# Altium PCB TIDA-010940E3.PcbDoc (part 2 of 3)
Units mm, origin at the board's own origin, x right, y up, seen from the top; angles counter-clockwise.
Board outline 71.12 x 63.5 mm, 2 copper layers (Top Layer, Bottom Layer), stack 1.382 mm thick; 136 components, 118 nets, 421 pads, 150 vias.
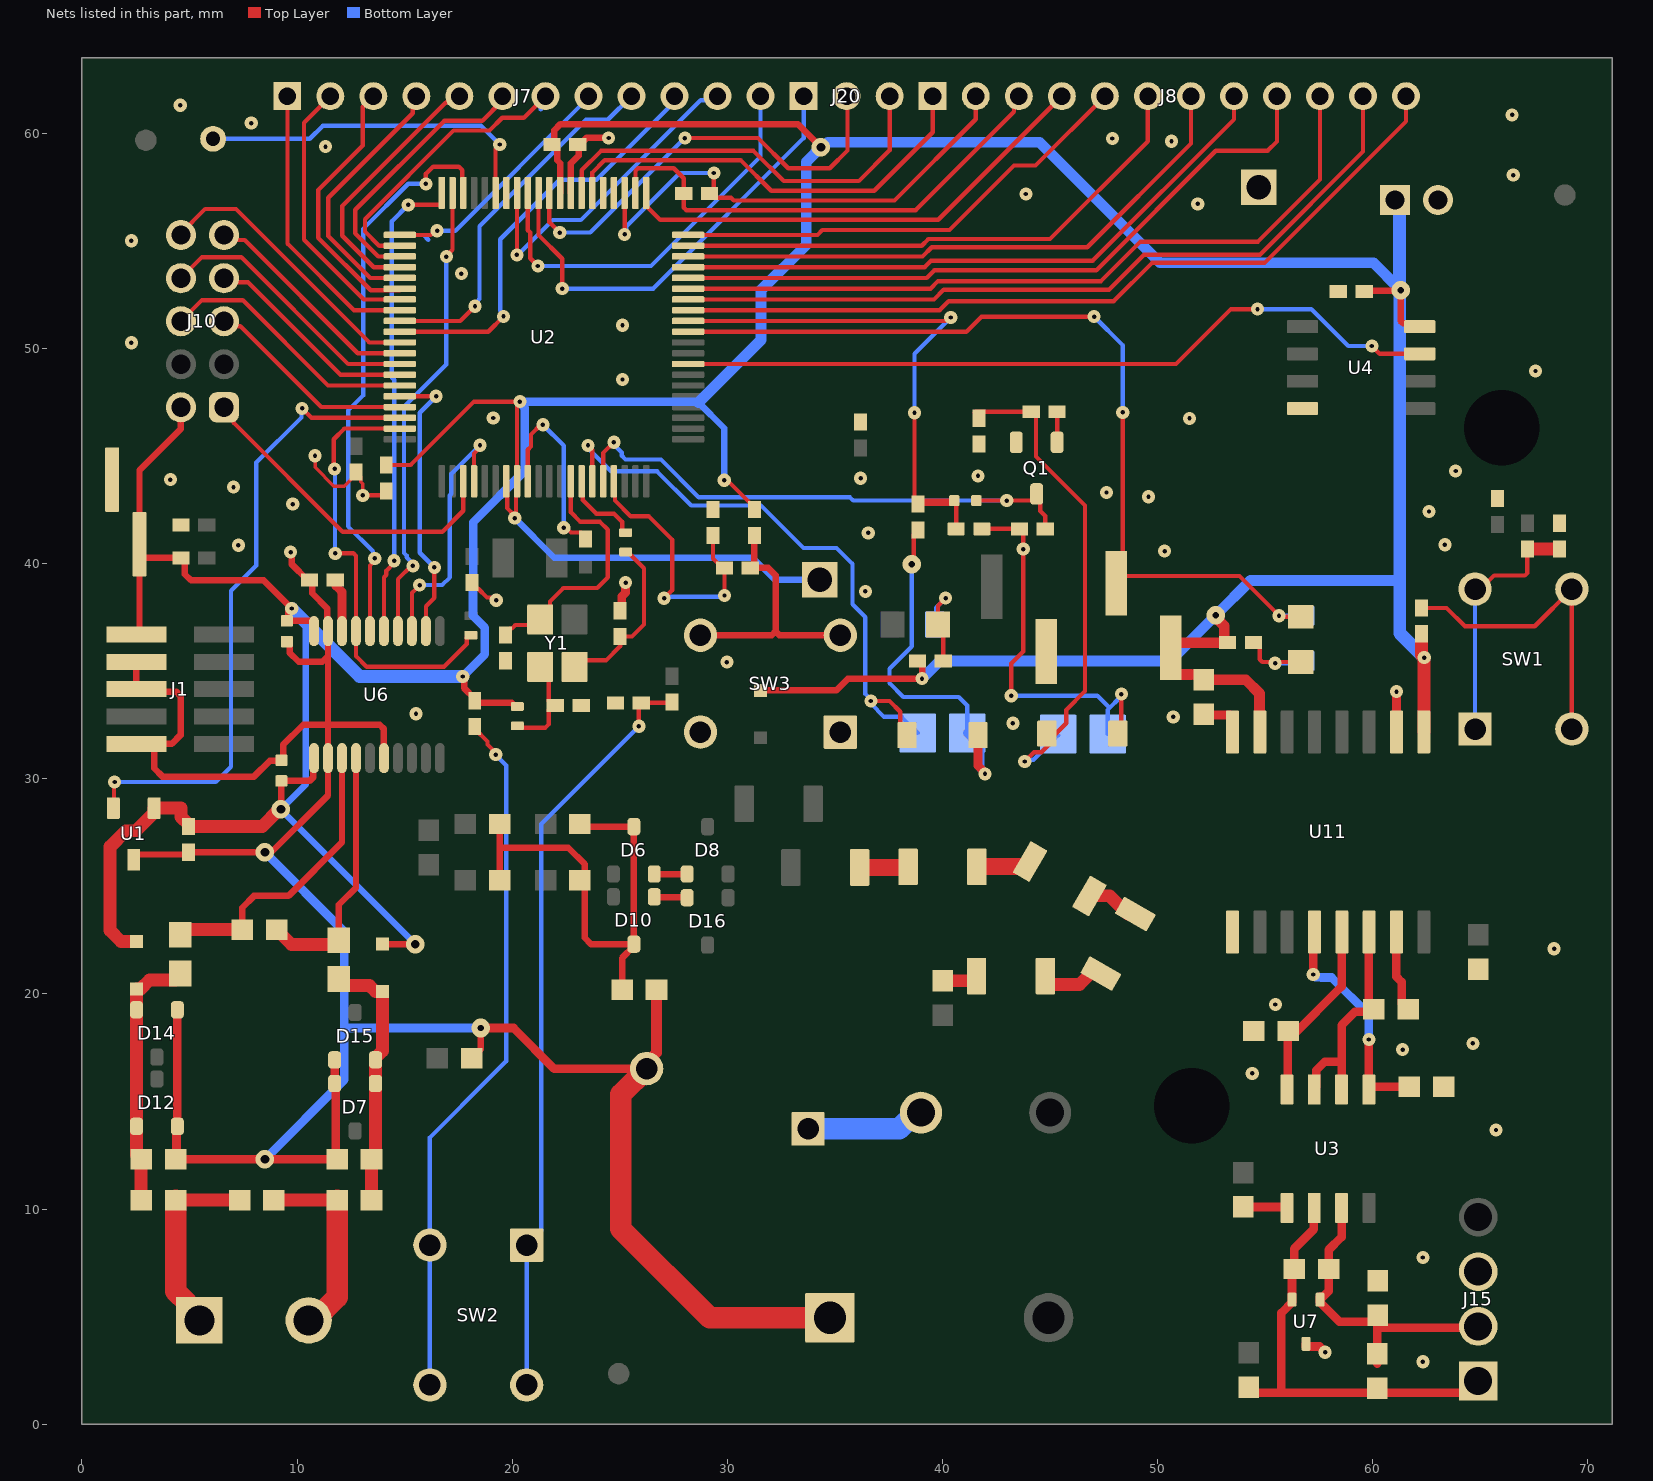
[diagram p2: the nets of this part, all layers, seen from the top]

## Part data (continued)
LBL1: library part CMP-0003625-1, "Thermal Transfer Printable Labels, 0.650\" W x 0.200\" H - 10,000 per roll", Manufacturer=Brady, Supplier Part Number 1=97C5133
Logo2: library part CMP-0074844-1
Logo3: library part CMP-0074847-1, "FCC_disclaimer"
Logo4: library part CMP-0074769-1
MP1 MP2 MP3 MP4: library part CMP-0097139-1, "Bumper Cylindrical, Flat Top 0.315\" Dia (8.00mm) Polyurethane Black", Digikey Part Number=3M156065-ND, Manufacturer=3M, Operating Temperature Range="+5°C to +52°C"
Q1: library part CMP-0000377-2, "Transistor, NPN, 30 V, 0.1 A, SOT-23", Manufacturer="ON Semiconductor", Supplier Part Number 1=BC848CLT1GOSCT-ND, Value1="0.1 A", Value2=800
R1: library part CMP-0026728-1, "RES, 220 k, 1%, 0.0625 W, 0402", Manufacturer="Yageo America", Power_W=62.5mW, Supplier Part Number 1=311-220KLRCT-ND, TempCo="100 ppm/C", Tolerance_%=1%, Value2=0.0625W, Value_Code=220k
R2: library part CMP-0026815-1, "RES, 100 k, 0.1%, 0.063 W, 0402", Manufacturer="Susumu Co Ltd", Power_W=63mW, Supplier Part Number 1=RG10P100KBCT-ND, TempCo="25 ppm/C", Tolerance_%=0.1%, Value2=0.063W, Value_Code=100k
R3: library part CMP-0049856-1, "Var MOV 460VAC/615VDC 5000A 750V Thru-Hole Radial Bulk", Clamping Voltage=1240V, Digikey Part Number=495-6498-ND, Manufacturer=TDK, Mouser Part Number=871-B72214S2461K101, Operating Temperature Range="-40°C to +105°C", ValueDisplayed=260pF, Varistor Voltage=750V, Voltage Tolerance=10%
R4 R6 R7 R74 R81: library part CMP-0025874-4, "RES, 0, 5%, 0.1 W, AEC-Q200 Grade 0, 0603", Manufacturer=Panasonic, Power_W=100mW, Supplier Part Number 1=P0.0GCT-ND, TempCo="600 ppm/C", Tolerance_%=5%, Value2=0.1W, Value_Code=0000, ValueDisplayed=0
R5 R9: library part CMP-0026658-1, "RES, 10.0 k, 1%, 0.1 W, 0402", Manufacturer=Panasonic, Power_W=100mW, Supplier Part Number 1=P10.0KLCT-ND, TempCo="100 ppm/C", Tolerance_%=1%, Value2=0.1W, Value_Code=10k0, ValueDisplayed=10.0k
R10 R11: library part CMP-0026729-1, "RES, 2.20 k, 1%, 0.063 W, 0402", Manufacturer="Yageo America", Power_W=63mW, Supplier Part Number 1=311-2.20KLRCT-ND, TempCo="100 ppm/C", Tolerance_%=1%, Value2=0.063W, Value_Code=2k20, ValueDisplayed=2.20k
R12 R13: library part CMP-0026940-2, "RES, 4.7 M, 5%, 0.063 W, AEC-Q200 Grade 0, 0402", Manufacturer=Vishay-Dale, Power_W=63mW, Supplier Part Number 1=541-4.7MJCT-ND, TempCo="200 ppm/C", Tolerance_%=5%, Value2=0.063W, Value_Code=4M70, ValueDisplayed=4.7M
R14: library part CMP-0026852-3, "RES, 1.0 k, 5%, 0.063 W, AEC-Q200 Grade 0, 0402", Manufacturer=Vishay-Dale, Power_W=63mW, Supplier Part Number 1=541-1.0KJCT-ND, TempCo="200 ppm/C", Tolerance_%=5%, Value2=0.063W, Value_Code=1k00, ValueDisplayed=1.0k
R15: library part CMP-0094948-1, "0 Ohms Jumper 0.1W, 1/10W Chip Resistor 0402 (1005 Metric) - Thick Film", Digikey Part Number=2679-CR0402-10W-000TTR-ND, Manufacturer=Venkel, Operating Temperature Range="-55°C to +155°C", Power_W=100mW
R16: library part CMP-0121809-1, "8.06 kOhms ±0.1% 0.063W, 1/16W Chip Resistor 0402 (1005 Metric) Automotive AEC-Q200 Thin Film", Digikey Part Number=P18117CT-ND, Manufacturer=Panasonic, Mouser Part Number=667-ERA-2ARB8061X, Operating Temperature Range="-55°C to +155°C", Power_W=63mW, TempCo=10ppm/°C, Tolerance_%=0.1%
R17: library part CMP-0026743-1, "RES, 820, 1%, 0.063 W, 0402", Manufacturer="Yageo America", Power_W=63mW, Supplier Part Number 1=311-820LRCT-ND, TempCo="100 ppm/C", Tolerance_%=1%, Value2=0.063W, Value_Code=820R, ValueDisplayed=820
R18 R86 R87: library part CMP-0026725-1, "RES, 1.00 k, 1%, 0.0625 W, 0402", Manufacturer="Yageo America", Power_W=62.5mW, Supplier Part Number 1=311-1.00KLRCT-ND, TempCo="100 ppm/C", Tolerance_%=1%, Value2=0.0625W, Value_Code=1k00, ValueDisplayed=1.00k
R19: library part CMP-0026680-1, "RES, 220, 1%, 0.1 W, AEC-Q200 Grade 0, 0402", Manufacturer=Panasonic, Power_W=100mW, Supplier Part Number 1=P220LCT-ND, TempCo="100 ppm/C", Tolerance_%=1%, Value2=0.1W, Value_Code=220R, ValueDisplayed=220
R20: library part CMP-0026979-3, "RES, 820, 5%, 0.063 W, AEC-Q200 Grade 0, 0402", Manufacturer=Vishay-Dale, Power_W=63mW, Supplier Part Number 1=541-820JCT-ND, TempCo="200 ppm/C", Tolerance_%=5%, Value2=0.063W, Value_Code=820R, ValueDisplayed=820
R21 R22 R23 R28 R29 R30: library part CMP-0018811-2, "RES, 330 k, 0.1%, 1 W, 1206", Manufacturer="Vishay Draloric", Power_W=1W, Supplier Part Number 1=541-2312-1-ND, TempCo="25 ppm/C", Tolerance_%=0.1%, Value_Code=330k
R24: library part CMP-0085526-3, "RES, 470, 5%, 5 W, AEC-Q200 Grade 0, Dia 7.5mm", Manufacturer=Vishay-Bccomponents, Power_W=5W, Tolerance_%=5%, Value_Code=470R, ValueDisplayed=470
R25 R26 R27: library part CMP-0120020-1, "0 Ohms Jumper Chip Resistor 0402 (1005 Metric) Metal Element", Digikey Part Number=36-5113-1-ND, Manufacturer="Keystone Electronics", Mouser Part Number=534-5113, Operating Temperature Range=to, Part Number=5113
R31 R36: library part CMP-0093507-1, "0 Ohms Jumper 1W Chip Resistor 1206 (3216 Metric) Automotive AEC-Q200, Current Sense Thick Film", Digikey Part Number=PMR18EZPJ000-ND, Manufacturer="Rohm Semiconductor", Max Current=38.7A, Mouser Part Number=755-PMR18EZPJ000, Operating Temperature Range="-55°C to +155°C"
R32 R33 R34 R35: library part CMP-0022895-5, "RES, 1.00 k, 1%, 0.1 W, 0603", Manufacturer=Yageo, Power_W=100mW, Supplier Part Number 1=311-1.00KHRCT-ND, TempCo="100 ppm/C", Tolerance_%=1%, Value2=0.1W, Value_Code=1k00, ValueDisplayed=1.00k
R37 R38: library part CMP-0092692-1, "RES SMD 0 OHM JUMPER 1/8W 0805", Digikey Part Number=311-0.0CRCT-ND, Manufacturer=Yageo, Mouser Part Number=603-RC0805FR-070RL, Operating Temperature Range="-55°C to +155°C", Power_W=125mW, Tolerance_%=1%
R46 R54: library part CMP-0025698-4, "RES, 100 k, 5%, 0.1 W, AEC-Q200 Grade 0, 0603", Manufacturer=Vishay-Dale, Power_W=100mW, Supplier Part Number 1=541-100KGCT-ND, TempCo="200 ppm/C", Tolerance_%=5%, Value2=0.1W, Value_Code=100k
R52 R55: library part CMP-0025817-4, "RES, 4.7 k, 5%, 0.1 W, AEC-Q200 Grade 0, 0603", Manufacturer=Vishay-Dale, Power_W=100mW, Supplier Part Number 1=541-4.7KGCT-ND, TempCo="200 ppm/C", Tolerance_%=5%, Value2=0.1W, Value_Code=4k70, ValueDisplayed=4.7k
R56: library part CMP-0024624-2, "RES, 120, 0.5%, 0.1 W, 0603", Manufacturer="Yageo America", Power_W=100mW, TempCo="50 ppm/C", Tolerance_%=0.5%, Value2=0.1W, Value_Code=120R, ValueDisplayed=120
R88: library part CMP-0026935-3, "RES, 47 k, 5%, 0.063 W, AEC-Q200 Grade 0, 0402", Manufacturer=Vishay-Dale, Power_W=63mW, Supplier Part Number 1=541-47KJCT-ND, TempCo="200 ppm/C", Tolerance_%=5%, Value2=0.063W, Value_Code=47k0, ValueDisplayed=47k
SW1 SW2 SW3: library part CMP-0008295-1, "Switch Tactile N.O. SPST Round Button PC Pins 0.05A 50VDC 2.45N Thru-Hole", Coil Resistance_ohm=100mΩ, Contact Current Rating=50mA, Digikey Part Number=EG1866-ND, Manufacturer=E-Switch, Mouser Part Number=612-TL1105D-250, Operating Force=250gf, Operating Temperature Range="-20°C to +70°C"
TP1: library part CMP-0055058-1, "PCB Pin, 0.46 Dia, Gold, TH", Manufacturer=Mill-Max, Supplier Part Number 1=ED1286-ND
U1: library part CMP-0078033-1, "Ultra-Low Power 1.65V to 5.5V Hall Effect Switch Sensor, DBZ0003A (SOT-23-3)", Alternate Manufacturer="Texas Instruments"
U2: library part CMP-0034581-1, Manufacturer="Texas Instruments", Operating Temperature Range=to
U3: library part CMP-0089978-1, "500 kbps RS-485 Transceivers With ±8-kV IEC ESD Protection", Manufacturer="Texas Instruments", Max Supply Voltage=5.5V, Min Supply Voltage=4.5V, Nominal Supply Current=275-440uA, Operating Temperature Range="-40°C to +125°C"
U4: library part CMP-0005381-2, "3V 8M-BIT SERIAL FLASH MEMORY WITH DUAL/QUAD SPI, SOIC-8", Manufacturer=Winbond
U6: library part CMP-0080543-1, "3-Channel, 24-Bit, Simultaneously-Sampling, Delta-Sigma ADC, PW0020A (TSSOP-20)", Alternate Manufacturer="Texas Instruments", Alternate PartNumber=ADS131M03IPWT
U7: library part CMP-0043100-2, "ESD Protection Array for AC Signal Data Interface, 2 Channels, -40 to +85 degC, 3-pin SC70 (DCK), Green (RoHS & no Sb/Br)", Breakdown Voltage(Min)(V)=+/-14, IO Capacitance(Typ)(pF)=15, IO Leakage Current(nA)=50, Manufacturer="Texas Instruments"
U11: library part CMP-0094636-1, Digikey Part Number=296-ISO6731DWRCT-ND, Manufacturer="Texas Instruments", Max Supply Voltage=5.5V, Min Supply Voltage=1.71V, Mouser Part Number=595-ISO6731DWR, Operating Temperature Range="-40°C to +125°C"
Y1: library part CMP-0085525-1, "Crystal, 16.384 MHz, 50 ppm, 10 pF, SMD", Frequency Stability="30 ppm", Frequency Tolerance="50 ppm", Frequency_Fixed=16.384MHz, Load Capacitance="10 pF", Manufacturer=Epson
Y2: library part CMP-0004693-2, "Crystal, 32.768 KHz, 12.5 pF, SMD", Frequency_Fixed=32.768kHz, Manufacturer=Epson
ZZ1: library part CMP-0003616-3
ZZ2: library part CMP-0077236-1
ZZ3: library part CMP-0077237-1
ZZ4: library part CMP-0077238-1

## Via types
v1: diameter 0.61, hole 0.203, Top Layer to Bottom Layer, tented both sides, 113 vias
v2: diameter 0.61, hole 0.203, Top Layer to Bottom Layer, 22 vias
v3: diameter 0.864, hole 0.406, Top Layer to Bottom Layer, 8 vias
v4: diameter 0.864, hole 0.3, Top Layer to Bottom Layer, tented both sides, 4 vias
v5: diameter 0.864, hole 0.406, Top Layer to Bottom Layer, tented both sides, 3 vias

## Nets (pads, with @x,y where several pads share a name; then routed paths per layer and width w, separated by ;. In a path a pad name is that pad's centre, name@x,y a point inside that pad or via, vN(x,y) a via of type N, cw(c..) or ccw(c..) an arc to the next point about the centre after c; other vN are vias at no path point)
485_D: R52.1 U3.4 U11.13 | length 8.3
  Top Layer w0.4: U3.4@56.007,15.552 56.04,15.585 56.04,18.242 R52.1@56.072,18.275 ; R52.1@56.276,18.072 58.547,20.343 U11.13@58.547,22.708
485_R: C85.2 U3.1 U11.12 | length 10.7
  Top Layer w0.4: v1(57.232,20.899) 57.232,22.663 U11.12@57.277,22.708 ; v1(59.817,17.882) U3.1@59.817,15.552 59.917,15.652 59.917,15.685 C85.2@61.7,15.685
  Bottom Layer w0.4: v1(57.232,20.899) 57.187,20.854 57.322,20.765 57.603,20.765 57.605,20.764 58.078,20.764 59.817,19.025 v1(59.817,17.882)
485_RE_DE: R55.1 U3.2 U3.3 U11.14 | length 10.5
  Top Layer w0.4: U3.3@57.277,15.552 57.377,15.652 57.377,16.458 57.758,16.839 58.447,16.839 ; U3.2@58.547,15.552 58.552,15.557 58.552,17.876 58.558,17.882 58.558,18.55 59.172,19.164 59.923,19.164 R55.1@60.038,19.279 59.817,19.5 U11.14@59.817,22.708
ACT: D1.1 J3.1 R38.1 U2.31 | length 42.4
  Top Layer w0.203: U2.31@28.178,50.774 41.113,50.774 41.813,51.475 v2(47.05,51.475) ; J3.1@48.066,39.092 48.066,39.226 J3.1@48.26,39.419 ; v2@48.371,47.147 48.371,39.53 J3.1@48.26,39.419 ; v1(55.641,37.575) 55.641,37.584 53.806,39.419 J3.1@48.26,39.419 ; v1@55.7,37.525 D1.1@56.65,37.525
  Bottom Layer w0.203: v2(47.05,51.475) 48.371,50.154 v2@48.371,47.147 ; v1(55.641,37.575) R38.1@56.7,37.575
  other v2: 48.375,47.025
ADC_DIN: U2.58 U6.16 | length 26.8
  Top Layer w0.203: U6.16@13.391,36.859 13.391,39.911 13.611,40.131 v1(13.611,40.241) ; v1(15.991,57.647) 15.991,58.113 16.327,58.449 17.517,58.449 17.687,58.279 17.687,57.265 U2.58@17.728,57.224
  Bottom Layer w0.203: v1(13.611,40.241) 13.533,40.319 13.533,40.567 12.375,41.725 12.375,47.113 13.071,47.809 13.071,55.546 15.172,57.647 v1(15.991,57.647)
ADC_DOUT: U2.60 U6.15 | length 22.5
  Top Layer w0.203: U6.15@14.041,36.859 14.041,39.368 14.155,39.482 14.155,39.665 14.511,40.021 v1(14.511,40.131) ; v1(15.172,56.673) 16.68,56.673 16.728,56.721 U2.60@16.728,57.224
  Bottom Layer w0.203: v1(14.511,40.131) 14.511,48.545 14.4,48.656 14.4,55.901 v1(15.172,56.673)
ADC_SPI0_CS1: U2.76 U6.12 | length 13.4
  Top Layer w0.2: U2.76@14.778,47.774 v1(16.468,47.774) ; U6.12@15.991,36.859 15.991,38.013 16.383,38.405 v1(16.383,39.825)
  Bottom Layer w0.2: v1(16.383,39.825) 15.705,40.503 15.705,47.012 v1(16.468,47.774)
ADC_SPI0_SCLK: U2.59 U6.14 | length 21.8
  Top Layer w0.2: U6.14@14.691,36.859 14.691,39.276 15.307,39.892 v1(15.385,39.892) ; v1(16.94,54.264) 16.94,54.298 17.228,54.586 U2.59@17.228,57.224
  Bottom Layer w0.2: v1(15.385,39.892) 15.385,40.002 15.096,40.292 15.096,40.373 14.975,40.494 14.975,47.288 16.94,49.253 v1(16.94,54.264)
BSL_Invoke: TP1.1 U2.55 | length 16.3
  Top Layer w0.2: U2.55@19.228,57.224 19.228,59.284 19.419,59.475 v2(19.424,59.475)
  Bottom Layer w0.2: TP1.1@6.1,59.74 10.593,59.74 11.203,60.35 18.549,60.35 v2(19.424,59.475)
CAP: C57.2 U6.18 | length 2.5
  Top Layer w0.4: C57.2@11.776,39.243 11.811,39.208 11.811,38.957 12.045,38.722 12.062,38.722 12.091,38.693 U6.18@12.091,36.859
CLKIN: R27.2 U2.79 U6.17 | length 20.6
  Top Layer w0.2: v1(11.75,44.4) 11.703,44.447 11.703,45.776 12.202,46.274 U2.79@14.778,46.274
  Top Layer w0.203: v1(11.776,40.474) 12.622,40.474 12.741,40.355 U6.17@12.741,36.859 12.741,35.7 13.234,35.207 16.83,35.207 17.884,36.261 17.884,36.571 17.982,36.669 R27.2@18.082,36.669
  Bottom Layer w0.2: v1(11.75,44.4) 11.763,44.387 11.763,40.487 v1(11.776,40.474)
D\R\D\Y\: U2.4 U6.13 | length 12.4
  Top Layer w0.2: U6.13@15.341,36.859 15.341,38.638 v1(15.702,38.999) ; U2.4@18.228,43.824 18.228,45.113 18.505,45.389 v1(18.505,45.5)
  Bottom Layer w0.2: v1(15.702,38.999) 16.746,38.999 17.104,39.357 17.104,43.177 17.175,43.248 17.175,44.17 v1(18.505,45.5)
DGND: C1.1 C2.2 C3.1 C4.1 C5.1 C6.2 C7.2 C8.2 C9.2 C10.2 C30.2 C34.1 C57.1 C62.1 C63.1 C64.2 C66.2 C67.2 C81.2 D7.2 D12.2 D14.1 D15.1 J1.3 J1.5 J1.9 J2.1 J4.1 J5.1 J11.2 J12.2 Q1.2 R2.1 R3.2 R4.1 R6.1 R12.1 R13.1 R20.1 SW3.1 SW3.2 U1.3 U2.9 U2.48 U4.4 U6.2 U6.6 U6.19 U11.2 U11.8 | length 150.5
  Top Layer w0.16: v1(10.837,45.012) 10.848,45 10.848,44.467 11.716,43.6 12.2,43.6 12.75,44.15 C62.1@12.75,44.25 12.97,44.03 12.97,43.797 13.055,43.712 v1(13.055,43.168)
  Top Layer w0.2: v1(13.055,43.168) 13.949,43.168 14.149,43.368 C64.2@14.149,43.378 ; C4.1@18.125,39.125 18.125,39.025 18.325,38.825 18.425,38.825 18.829,38.421 v2@19.131,38.421 ; U2.9@20.728,43.824 20.728,45.286 20.878,45.436 20.878,46 21.328,46.45 v1(21.425,46.45) ; v1(22.395,41.666) 22.506,41.666 22.733,41.439 23.2,41.439 23.2,41.225 C5.1@23.286,41.139
  Top Layer w0.3: J4.1@1.235,44.474 J4.1@1.41,44.299 ; U1.3@2.413,26.232 2.413,26.328 2.563,26.478 4.853,26.478 C2.2@4.953,26.578 v5(8.509,26.578) 8.798,26.578 11.441,29.221 U6.2@11.441,30.959 11.441,32.512 ; J1.9@2.537,31.623 J1.9@3.143,31.623 ; J1.3@2.537,35.433 J1.5@2.537,34.163 2.65,34.05 4.382,34.05 4.59,33.842 4.59,32.027 4.186,31.623 J1.9@3.143,31.623 ; C3.1@9.512,36.373 C3.1@9.525,36.373 ; C3.1@9.654,36.256 9.654,35.86 10.082,35.433 11.176,35.433 11.441,35.698 ; v1(9.705,40.533) 9.764,40.474 9.764,39.955 10.476,39.243 C57.1@10.576,39.243 10.703,39.116 10.703,38.62 11.412,37.911 11.412,36.888 U6.19@11.441,36.859 11.441,35.698 ; U6.6@14.041,30.959 14.041,32.314 13.843,32.512 11.441,32.512 ; R4.1@18.125,17 18.15,17 18.475,17.325 18.475,17.35 18.542,17.417 v4(18.542,18.415) ; U2.48@22.728,57.224 22.728,58.597 23.085,58.954 23.085,59.44 C63.1@23.05,59.475 23.15,59.475 23.455,59.78 24.475,59.78 v1(24.48,59.775) ; J1.9@3.143,31.623 3.363,31.403 3.363,30.48 3.744,30.099 8.001,30.099 8.742,30.84 9.252,30.84 9.354,30.941 9.354,31.579 10.287,32.512 11.441,32.512 ; 11.441,32.512 11.441,35.698
  Top Layer w0.4: D14.1@4.44,19.261 D12.2@4.44,13.843 4.398,13.801 4.398,12.361 C30.2@4.356,12.319 v3(8.509,12.319) C34.1@11.862,12.319 11.806,12.375 11.806,15.776 D7.2@11.75,15.832 D15.1@11.75,16.934 ; v4(18.542,18.415) 20.06,18.415 21.95,16.525 R3.2@26.25,16.525 ; C67.2@25.019,37.811 25.102,37.894 25.102,38.476 25.267,38.642 25.267,39.11 v1(25.273,39.116) ; v1(36.195,43.962) v1@36.235,44.002 ; C81.2@52.142,33.001 52.18,32.962 53.38,32.962 53.48,32.862 U11.8@53.48,32.175 ; U11.2@61.1,32.175 v1(61.1,34.045)
  Top Layer w0.5: R3.2@26.25,16.525 26.25,16.809 26.708,17.267 R6.1@26.708,20.193
  Top Layer w1: R3.2@26.25,16.525 25.05,15.325 25.05,9.075 29.175,4.95 J2.1@34.77,4.95
  Bottom Layer w0.2: 15.051,55.274 15.877,55.274 16.099,55.052 ; v1(21.425,46.45) 22.395,45.48 v1(22.395,41.666)
  Bottom Layer w0.4: v3(8.509,12.319) 12.2,16.01 12.2,18.415 ; v5(8.509,26.578) 12.2,22.887 12.2,18.415 ; v4(18.542,18.415) 12.2,18.415
  other v1: 43.27,32.575 50.726,32.874 15.528,33.02 29.978,35.417 36.415,38.708 50.325,40.575 7.275,40.85 63.35,40.875 36.55,41.425 62.611,42.418 9.805,42.761 49.573,43.102 47.625,43.3 7.05,43.55 4.112,43.902 41.65,44.075 63.85,44.3 51.477,46.748 19.122,46.766 25.125,48.556 67.559,48.95 2.3,50.262 25.125,51.074 17.642,53.474 2.3,55 51.864,56.719 43.875,57.175 66.525,58.05 11.326,59.375 50.642,59.625 47.895,59.752 7.875,60.471 66.475,60.85 4.575,61.298
  other v2: 19.258,38.294
DRV_OUT: U1.2 U2.78 | length 29.7
  Top Layer w0.2: U1.2@1.463,28.632 1.493,28.663 1.493,29.814 v1(1.524,29.845) ; v1@10.262,47.238 v1(10.236,47.212) 10.674,46.774 U2.78@14.778,46.774
  Bottom Layer w0.2: v1(1.524,29.845) 6.223,29.845 6.936,30.558 6.936,38.739 8.109,39.912 8.109,44.693 10.204,46.789 10.204,47.181 v1(10.236,47.212)
DVDD: C1.2 C2.1 C3.2 C10.1 C63.2 C64.1 C81.1 D3.1 D5.1 D13.1 J1.1 J3.2 J4.2 J6.1 J10.2 J11.1 R1.2 R5.2 R9.2 R25.2 R86.2 R87.2 R88.2 U1.1 U2.7 U2.8 U2.49 U4.8 U6.1 U6.20 U11.1 U11.7 | length 265.8
  Top Layer w0.2: C64.1@14.149,44.578 15.28,44.578 18.226,47.524 v1(20.361,47.524) ; U2.7@19.728,43.824 19.767,43.786 19.767,42.58 v1@20.122,42.225 ; v1@20.178,42.17 20.178,43.774 U2.8@20.228,43.824 v1@20.228,47.28 ; v1@30.072,43.793 31.256,42.609 R1.2@31.256,42.509
  Top Layer w0.3: J1.1@2.537,36.703 2.68,36.846 J4.2@2.68,40.434 ; J10.2@4.604,47.262 4.604,46.262 2.68,44.339 J4.2@2.68,40.9 J4.2@2.68,40.434 ; v3(9.252,28.575) 9.263,28.586 9.263,29.885 C1.2@9.273,29.896 10.581,29.896 10.762,30.077 10.762,30.415 10.791,30.443 U6.1@10.791,30.959 ; U6.20@10.791,36.859 10.791,37.269 10.722,37.338 C3.2@9.525,37.338 9.598,37.411 9.598,37.755 v1(9.754,37.911) 8.446,39.218 5.077,39.218 4.786,39.509 4.786,40.109 4.636,40.259 R88.2@4.607,40.259 2.855,40.259 J4.2@2.68,40.434 ; D13.1@13.97,22.309 v3(15.494,22.309) v3@15.43,22.246 ; v1(17.705,34.753) 17.765,34.694 17.765,34.215 18.26,33.72 R9.2@18.26,33.62 18.36,33.52 19.976,33.52 20.14,33.356 R25.2@20.24,33.356 ; C63.2@21.85,59.475 C63.2@21.95,59.475 ; U2.49@22.228,57.224 22.228,58.61 22.1,58.738 22.1,59.325 C63.2@21.95,59.475 ; D3.1@31.547,34.102 35.058,34.102 35.606,34.65 v1(39.05,34.65) 39.05,35.321 38.9,35.471 R87.2@38.836,35.471 ; v5(34.35,59.35) 33.275,60.425 22.246,60.425 21.95,60.129 C63.2@21.95,59.475 ; C10.1@59.597,52.652 59.626,52.681 v4@61.262,52.681 ; v4(61.291,52.71) 61.291,51.275 61.404,51.162 62.031,51.162 U4.8@62.181,51.012
  Top Layer w0.5: 51.54,34.842 50.856,34.842 50.606,35.092 J3.2@50.606,36.092 50.836,36.322 R86.2@53.148,36.322 ; C81.1@51.718,34.842 C81.1@52.142,34.842 ; C81.1@52.142,34.601 54.099,34.601 54.737,33.963 U11.7@54.737,32.184 ; v4(52.705,37.592) 52.705,37.494 53.098,37.101 53.098,36.372 R86.2@53.148,36.322 ; R86.2@53.248,36.322 R86.2@53.148,36.322
  Top Layer w0.6: D5.1@2.54,22.436 1.821,22.436 1.316,22.941 1.316,26.843 2.056,27.583 2.514,27.583 3.363,28.432 U1.1@3.363,28.632 4.602,28.632 4.602,28.229 4.953,27.878 C2.1@4.953,27.778 8.384,27.778 9.181,28.575 v3(9.252,28.575) ; v1@62.267,35.749 R5.2@62.267,36.738 ; U11.1@62.37,32.184 62.37,34.24 62.387,34.258 v1@62.387,35.628
  Bottom Layer w0.3: 10.414,37.25 10.414,29.737 v3(9.252,28.575) 9.252,28.563 15.494,22.321 v3(15.494,22.309) ; v1(20.122,42.114) 21.959,40.276 31.171,40.276 32.205,39.242 J6.1@34.29,39.242 ; 28.661,47.483 29.858,46.286 v1(29.858,43.871)
  Bottom Layer w0.4: v1(17.705,34.753) 18.728,35.776 18.728,37.023 18.182,37.569 18.182,38.682 18.2,38.7 18.2,41.926 20.589,44.315 20.589,47.239 20.361,47.467 v1(20.361,47.524) ; v1@20.589,47.524 28.62,47.524
  Bottom Layer w0.5: 28.661,47.483 31.57,50.392 31.57,52.709 33.664,54.803 33.664,58.664 v5@34.401,59.401 ; v5@34.673,59.575 44.507,59.575 50.107,53.975 60.026,53.975 61.24,52.761 v4(61.291,52.71) ; v1(39.05,34.65) 39.871,35.471 50.584,35.471 v4(52.705,37.592) 54.32,39.207 61.25,39.207
  Bottom Layer w0.6: v1(9.754,37.911) 10.414,37.25 12.908,34.756 v1@17.696,34.756 ; J11.1@61.031,56.898 61.24,56.688 v4@61.24,52.761 ; v4(61.291,52.71) 61.25,52.67 61.25,39.207 61.25,36.763 v1(62.387,35.626)
GND_ISO_RS: C80.2 C85.1 C86.2 J15.3 R46.1 R52.2 R55.2 U3.5 U7.3 U11.9 U11.15 | length 7.6
  Top Layer w0.4: U11.9@53.404,22.644 U11.9@53.467,22.708 ; C86.2@53.975,10.097 55.962,10.097 U3.5@56.007,10.052 ; U7.3@56.896,3.738 56.896,3.613 57.521,3.613 57.671,3.463 57.785,3.349 v1(57.785,3.344) ; R46.1@60.219,6.658 R46.1@60.434,6.872 ; U11.15@61.087,22.708 61.087,20.809 61.338,20.558 61.338,19.554 61.613,19.279 R55.2@61.638,19.279 R55.2@61.689,19.228 ; J15.3@64.682,6.872 J15.3@64.897,7.087
  other v1: 62.325,2.9 62.325,7.75 65.725,13.675 54.397,16.307 61.388,17.408 64.65,17.7 55.471,19.507 68.425,22.098
HFO: C67.1 R26.1 Y1.1 | length 8
  Top Layer w0.2: Y1.1@22.9,35.5 24.357,35.5 25.019,36.162 C67.1@25.019,36.611 25.573,36.611 26.129,37.167 26.129,39.781 25.373,40.538 R26.1@25.273,40.538
HFXIN: C6.1 U2.13 Y1.3 | length 11.8
  Top Layer w0.2: C6.1@19.685,36.684 19.685,36.784 19.885,36.984 19.985,36.984 20.149,37.148 20.8,37.148 21.3,37.648 21.404,37.648 21.756,38 21.756,38.24 22.38,38.863 23.95,38.863 24.448,39.361 24.448,41.568 24.078,41.938 23.17,41.938 22.728,42.38 U2.13@22.728,43.824
HFXOUT: R26.2 U2.14 | length 3.7
  Top Layer w0.2: U2.14@23.228,43.824 23.278,43.774 23.278,42.952 23.912,42.318 24.736,42.318 25.116,41.938 25.116,41.538 25.216,41.438 R26.2@25.273,41.438
HOLD_FLASH: U2.28 U4.7 | length 35.9
  Top Layer w0.203: U2.28@28.178,49.274 50.854,49.274 53.406,51.826 v1(54.643,51.826) ; v2(59.956,50.11) 60.324,49.742 U4.7@62.181,49.742
  Bottom Layer w0.203: v1(54.643,51.826) 57.137,51.826 58.853,50.11 v2(59.956,50.11)
I_N: C38.2 R35.2 U6.4 | length 12.1
  Top Layer w0.3: R35.2@11.938,22.49 11.938,22.79 11.938,24.136 12.741,24.939 U6.4@12.741,30.959
  Top Layer w0.6: C38.2@9.055,22.987 9.08,22.987 9.255,22.812 9.255,22.787 9.746,22.296 11.744,22.296 R35.2@11.938,22.49
I_P: C38.1 R34.2 U6.3 | length 13.8
  Top Layer w0.3: C38.1@7.455,22.987 7.455,24.005 8,24.55 9.6,24.55 12.091,27.041 U6.3@12.091,30.959
  Top Layer w0.6: R34.2@4.572,22.744 4.572,22.762 4.797,22.987 C38.1@7.455,22.987
I_PA_N: C34.2 D7.1 D13.2 D15.2 R35.1 R81.2 | length 12.2
  Top Layer w0.6: R35.1@11.938,20.69 11.938,20.615 12.163,20.39 13.363,20.39 13.644,20.109 D13.2@13.97,20.109 13.97,17.354 13.65,17.034 D15.2@13.65,16.934 D7.1@13.65,15.832 13.65,12.494 13.475,12.319 C34.2@13.462,12.319 R81.2@13.462,10.414
I_PA_P: C30.1 D5.2 D12.1 D14.2 R34.1 R74.2 | length 12.3
  Top Layer w0.6: R74.2@2.756,10.414 C30.1@2.756,12.319 2.731,12.319 2.54,12.51 D12.1@2.54,13.843 D14.2@2.54,19.261 D5.2@2.54,20.236 2.739,20.236 3.147,20.644 4.347,20.644 4.572,20.869 R34.1@4.572,20.944
I_Phase_A_N: C31.2 J14.2 R81.1 | length 9.2
  Top Layer w0.6: C31.2@8.928,10.414 R81.1@11.862,10.414
  Top Layer w1: J14.2@10.541,4.826 10.795,4.826 11.862,5.893 R81.1@11.862,10.414
I_Phase_A_P: C31.1 J14.1 R74.1 | length 9
  Top Layer w0.6: R74.1@4.356,10.414 C31.1@7.328,10.414
  Top Layer w1: R74.1@4.356,10.414 4.356,6.185 4.886,5.655 4.886,5.401 J14.1@5.461,4.826
ISO_A: C84.1 J15.1 R54.1 R56.2 U3.6 U7.2 | length 20.3
  Top Layer w0.4: R54.1@54.047,1.461 55.753,1.461 ; U3.6@57.277,10.052 57.253,10.028 57.253,9.057 56.35,8.154 R56.2@56.35,7.214 56.246,7.11 U7.2@56.246,5.788 56.246,5.663 55.753,5.17 55.753,1.461 ; J15.1@64.897,2.007 64.351,1.461 60.198,1.461 55.753,1.461
ISO_B: C84.2 J15.2 R46.2 R56.1 U3.7 U7.1 | length 14.5
  Top Layer w0.4: U3.7@58.547,10.052 58.547,8.7 57.95,8.103 R56.1@57.95,7.214 57.95,6.192 57.671,5.913 57.546,5.913 U7.1@57.546,5.788 57.546,5.663 58.446,4.763 R46.2@59.944,4.763 ; C84.2@60.198,2.807 60.209,2.817 60.209,4.483 60.209,5.047 R46.2@60.219,5.058 ; 60.299,4.483 64.834,4.483 J15.2@64.897,4.547
LCD_EN: U2.44
LCD_SEG3: J8.12 U2.33 | length 38.2
  Top Layer w0.2: U2.33@28.178,51.774 39.866,51.774 40.288,52.197 47.963,52.197 49.741,53.975 54.969,53.975 61.546,60.552 J8.12@61.546,61.722
LCD_SEG4: J8.11 U2.34 | length 36.8
  Top Layer w0.2: U2.34@28.178,52.274 39.604,52.274 40.054,52.724 47.738,52.724 49.368,54.355 54.755,54.355 59.546,59.146 J8.11@59.546,61.722
LCD_SEG5: J8.10 U2.35 | length 35.3
  Top Layer w0.2: U2.35@28.178,52.774 39.439,52.774 39.79,53.125 47.368,53.125 49.206,54.962 54.662,54.962 57.546,57.846 J8.10@57.546,61.722
LCD_SEG6: J8.9 U2.36 | length 32.1
  Top Layer w0.2: U2.36@28.178,53.274 39.267,53.274 39.618,53.625 47.147,53.625 52.704,59.182 55.112,59.182 55.546,59.616 J8.9@55.546,61.722
LCD_SEG7: J8.8 U2.37 | length 29.3
  Top Layer w0.2: U2.37@28.178,53.774 39.169,53.774 39.47,54.075 46.978,54.075 53.546,60.643 J8.8@53.546,61.722
LCD_SEG8: J8.7 U2.38 | length 27.7
  Top Layer w0.2: U2.38@28.178,54.274 39.075,54.274 39.501,54.7 46.725,54.7 51.546,59.521 J8.7@51.546,61.722
LCD_SEG9: J8.6 U2.39 | length 25.5
  Top Layer w0.2: U2.39@28.178,54.774 39.038,54.774 39.343,55.08 45.001,55.08 49.546,59.625 J8.6@49.546,61.722
LCD_SEG10: J8.5 U2.40 | length 22
  Top Layer w0.2: U2.40@28.178,55.274 34.189,55.274 34.415,55.5 40.326,55.5 43.327,58.501 44.325,58.501 J8.5@47.546,61.722
LCD_SEG11: J8.4 U2.41 | length 22.6
  Top Layer w0.2: U2.41@26.228,57.224 26.228,56.624 26.877,55.975 39.799,55.975 J8.4@45.546,61.722
LCD_SEG12: C68.1 J8.3 U2.42 | length 23
  Top Layer w0.2: U2.42@25.728,57.224 25.728,58.253 25.845,58.37 27.508,58.37 27.975,57.903 27.975,56.542 28.092,56.425 38.755,56.425 43.326,60.996 43.326,61.502 J8.3@43.546,61.722
LCD_SEG13: C68.2 J8.2 U2.43 | length 23.2
  Top Layer w0.2: v2(25.228,55.298) U2.43@25.228,57.224 ; v1(29.375,58.15) 29.375,57 30.175,57 30.3,56.875 37.77,56.875 41.546,60.651 J8.2@41.546,61.722
  Bottom Layer w0.2: v2(25.228,55.298) 25.306,55.376 25.306,55.67 27.786,58.15 v1@29.175,58.15
LCD_SEG14: J8.1 U2.46 | length 20.4
  Top Layer w0.2: U2.46@23.728,57.224 23.728,58.173 24.305,58.75 30.618,58.75 32.043,57.325 36.825,57.325 39.546,60.046 J8.1@39.546,61.722
LCD_SEG15: J20.3 U2.47 | length 19.4
  Top Layer w0.2: U2.47@23.228,57.224 23.228,58.278 24.13,59.18 31.22,59.18 32.625,57.775 36.113,57.775 37.543,59.205 J20.3@37.543,61.722
LCD_SEG16: J20.2 U2.50 | length 20.7
  Top Layer w0.2: U2.50@21.728,57.224 21.728,55.867 v2(22.212,55.382) ; v2(28.025,59.774) 31.427,59.774 32.83,58.372 34.756,58.372 35.584,59.199 35.584,61.681 J20.2@35.543,61.722
  Bottom Layer w0.2: v2(22.212,55.382) 23.633,55.382 v2(28.025,59.774)
LCD_SEG17: J20.1 U2.51 | length 21
  Top Layer w0.2: U2.51@21.228,57.224 21.228,55.263 22.325,54.166 v1(22.325,52.775)
  Bottom Layer w0.2: v1(22.325,52.775) 26.55,52.775 33.546,59.771 33.546,61.425 J20.1@33.546,61.722
LCD_SEG18: J7.12 U2.52 | length 18.8
  Top Layer w0.2: U2.52@20.728,57.224 20.728,55.49 20.836,55.382 20.836,54.188 v1(21.194,53.83)
  Bottom Layer w0.2: v1(21.194,53.83) 26.455,53.83 31.546,58.921 J7.12@31.546,61.722
LCD_SEG19: J7.11 U2.53 | length 15.3
  Top Layer w0.2: v1(20.219,54.343) 20.223,54.348 20.223,57.22 U2.53@20.228,57.224
  Bottom Layer w0.2: v1(20.219,54.343) 20.259,54.343 21.883,55.967 23.194,55.967 28.758,61.531 29.355,61.531 J7.11@29.546,61.722
LCD_SEG25: J7.8 U2.61 | length 11.6
  Top Layer w0.2: U2.61@14.778,55.274 16.21,55.274 16.402,55.465 v2(16.512,55.465)
  Bottom Layer w0.2: v2(16.512,55.465) 17.36,55.465 23.319,61.424 23.543,61.424 J7.8@23.543,61.722
LCD_SEG26: J7.7 U2.62 | length 13.9
  Top Layer w0.2: U2.62@14.778,54.774 13.818,54.774 13.156,55.436 13.156,56.001 17.28,60.125 18.946,60.125 19.543,60.722 20.543,60.722 J7.7@21.543,61.722
  Bottom Layer w0.2: 21.333,61.098 21.333,61.512 J7.7@21.543,61.722
LCD_SEG27: J7.2 U2.67 | length 12.8
  Top Layer w0.2: J7.2@11.557,61.722 10.325,60.49 10.325,55.049 13.1,52.274 U2.67@14.778,52.274
LCD_SEG28: J7.1 U2.68 | length 13.4
  Top Layer w0.2: J7.1@9.557,61.722 9.557,54.868 12.651,51.774 U2.68@14.778,51.774
LCD_SEG29: J7.9 U2.69 | length 17.2
  Top Layer w0.2: U2.69@14.778,51.274 17.59,51.274 v2(18.275,51.959) v2@18.275,51.912
  Bottom Layer w0.2: v2(18.275,51.959) 18.275,52.07 18.436,52.23 18.436,52.253 18.479,52.297 18.479,55.673 23.431,60.625 24.446,60.625 J7.9@25.543,61.722
LCD_SEG30: J10.5 U2.77 | length 9.8
  Top Layer w0.2: J10.5@6.604,51.262 6.834,51.033 7.369,51.033 11.127,47.274 U2.77@14.778,47.274
LCD_SEG33: J7.6 U2.63 | length 12.8
  Top Layer w0.2: U2.63@14.778,54.274 13.78,54.274 12.708,55.346 12.708,56.439 16.844,60.575 18.608,60.575 19.543,61.51 J7.6@19.543,61.722
LCD_SEG34: J7.5 U2.64 | length 12.2
  Top Layer w0.2: U2.64@14.778,53.774 13.571,53.774 12.106,55.239 12.106,56.615 16.906,61.415 16.938,61.415 17.245,61.722 J7.5@17.543,61.722
LCD_SEG35: J7.4 U2.65 | length 12.3
  Top Layer w0.2: U2.65@14.778,53.274 13.402,53.274 11.453,55.224 11.453,57.003 15.38,60.93 15.38,61.559 J7.4@15.543,61.722
LCD_SEG36: J7.3 U2.66 | length 12.4
  Top Layer w0.2: J7.3@13.557,61.722 13.059,61.224 13.059,59.432 10.992,57.365 10.992,55.136 13.423,52.704 U2.66@14.778,52.704
LCD_SEG39: J10.9 U2.72 | length 10.4
  Top Layer w0.2: J10.9@6.604,55.262 6.834,55.033 7.567,55.033 12.826,49.774 U2.72@14.778,49.774
LCD_SEG40: J10.8 U2.73 | length 12.6
  Top Layer w0.2: J10.8@4.604,53.262 5.582,54.24 6.196,54.24 6.198,54.242 7.408,54.242 12.376,49.274 U2.73@14.778,49.274
LCD_SEG41: J10.7 U2.74 | length 10
  Top Layer w0.2: J10.7@6.604,53.262 6.79,53.076 7.724,53.076 12.026,48.774 U2.74@14.778,48.774
LCD_SEG42: J10.6 U2.75 | length 12.2
  Top Layer w0.2: J10.6@4.604,51.262 5.584,52.242 7.475,52.242 11.443,48.274 U2.75@14.778,48.274
LCD_SEG44: J10.10 U2.71 | length 13.3
  Top Layer w0.2: J10.10@4.604,55.262 4.604,55.348 5.731,56.475 7.163,56.475 13.363,50.274 U2.71@14.778,50.274
LCD_SEG45: J7.10 U2.70 | length 19.8
  Top Layer w0.2: U2.70@14.778,50.774 18.888,50.774 v2(19.599,51.485)
  Bottom Layer w0.2: v2(19.599,51.485) 19.599,51.596 19.45,51.745 19.45,55.073 22.212,57.835 23.92,57.835 27.543,61.458 J7.10@27.543,61.722
LCD_SEG46: J10.1 U2.3 | length 15.4
  Top Layer w0.2: J10.1@6.604,47.262 7.05,46.817 7.05,46.55 12.12,41.48 16.756,41.48 17.728,42.452 U2.3@17.728,43.824
LCD_SON: U2.45
LCDLFCLK: U2.54
M0_RX: Q1.3 R16.1 R18.1 U2.16 | length 26.3
  Top Layer w0.2: U2.16@24.228,43.824 24.228,45.135 v1(24.728,45.635) ; R16.1@41.57,42.926 v1(42.986,42.926) 44.181,42.926 44.377,43.122 Q1.3@44.377,43.236 44.546,43.066 44.546,42.445 44.777,42.214 R18.1@44.777,41.614
  Bottom Layer w0.2: v1(24.728,45.635) 24.728,45.524 25.089,45.163 25.089,45.015 25.268,44.836 26.914,44.836 28.675,43.075 35.7,43.075 35.849,42.926 v1(42.986,42.926)
M0_TX: D9.1 R36.1 U2.15 | length 29
  Top Layer w0.2: v1(23.525,45.49) 23.728,45.287 U2.15@23.728,43.824 ; v1(36.671,33.614) 37.537,33.614 38.04,33.111 38.04,32.525 38.44,32.125 D9.1@38.675,32.125
  Bottom Layer w0.2: v1(23.525,45.49) 23.394,45.49 23.46,45.425 24.602,44.283 26.738,44.283 28.326,42.695 31.567,42.695 33.538,40.724 35.077,40.724 35.815,39.985 35.815,38.104 36.415,37.505 36.415,33.936 36.671,33.68 v1(36.671,33.614) ; v1@36.671,33.489 37.286,32.874 38.101,32.874 R36.1@38.85,32.125
M0_VCC_OPTO: R15.2 R16.2 R17.2 U2.32 | length 26.4
  Top Layer w0.2: U2.32@28.178,51.274 40.114,51.274 40.275,51.435 v1(40.386,51.435) ; v1(38.698,47.009) 38.698,42.926 R16.2@40.458,42.926 ; R17.2@38.862,42.764 40.296,42.764 R16.2@40.458,42.926 ; R15.2@40.633,41.614 40.633,42.926 R16.2@40.458,42.926
  Bottom Layer w0.2: v1(38.698,47.009) 38.698,49.747 v1(40.386,51.435)
MENU_SW: C7.1 R14.2 U2.17 | length 13.1
  Top Layer w0.2: U2.17@24.728,43.824 24.778,43.774 24.778,42.93 25.515,42.193 26.353,42.193 27.434,41.112 27.434,38.761 v1(27.062,38.389) ; C7.1@29.337,41.31 29.337,40.229 29.766,39.8 R14.2@29.866,39.8 v1(29.866,38.514)
  Bottom Layer w0.2: v1(27.062,38.389) 27.125,38.451 29.804,38.451 v1(29.866,38.514)
NetC9_1: C9.1 R25.1 Y1.4 | length 5
  Top Layer w0.2: R25.1@20.24,32.456 20.321,32.375 21.544,32.375 21.706,32.537 21.706,33.201 21.78,33.275 C9.1@21.906,33.401 ; Y1.4@21.3,35.5 21.706,35.094 21.706,33.601 C9.1@21.906,33.401 ; C9.1@22.006,33.401 C9.1@21.906,33.401
NetC29_1: C29.1 C54.2 D6.3 D10.3 R6.2 R32.1 R33.1 | length 23.1
  Top Layer w0.3: C29.1@19.417,25.273 19.417,26.797 ; C54.2@19.417,27.896 19.417,26.797 ; R32.1@23.152,27.686 23.236,27.77 D6.3@25.654,27.77 D10.3@25.654,22.311 ; R6.2@25.108,20.193 25.108,21.665 25.654,22.211 D10.3@25.654,22.311 ; 19.417,26.797 22.606,26.797 23.368,26.035 23.368,22.606 23.663,22.311 D10.3@25.654,22.311
NetD1_2: D1.2 R38.2 R86.1 | length 4.2
  Top Layer w0.203: R86.1@54.448,36.322 54.548,36.322 54.746,36.124 54.746,35.544 54.865,35.425 D1.2@56.65,35.425
  Bottom Layer w0.203: v1(55.46,35.367) 56.592,35.367 R38.2@56.7,35.475
NetD2_2: D2.2 R37.2 R87.1 | length 4.6
  Top Layer w0.2: R87.1@40.036,35.471 40.036,36.925 D2.2@39.795,37.166 39.795,38.041 v1(40.145,38.391)
  Bottom Layer w0.2: R37.2@39.641,37.166 39.703,37.228 39.703,37.949 v1(40.145,38.391)
NetD4_1: D4.1 R15.1 R18.2 R31.2 | length 18.7
  Top Layer w0.2: R15.1@41.833,41.614 R18.2@43.477,41.614 ; v2(43.194,33.858) 43.194,35.356 43.752,35.913 v1(43.752,40.667) 43.752,41.44 R18.2@43.577,41.614 ; D4.1@47.825,32 48.311,32.486 v2(48.311,33.931)
  Bottom Layer w0.2: v2(43.194,33.858) 47.197,33.858 47.725,33.33 ; R31.2@47.675,32.075 47.675,33.195 48.311,33.831 v2(48.311,33.931)
NetD4_2: D4.2 R19.2 R20.2 R31.1 | length 23.4
  Top Layer w0.2: R20.2@41.483,47.004 41.532,47.053 44.146,47.053 44.346,46.853 44.346,44.977 46.625,42.698 46.625,34.069 45.75,33.194 45.75,32.575 45.175,32 45.175,31.803 44.6,31.228 44.25,31.228 v2(43.822,30.8)
  Bottom Layer w0.2: v2(43.822,30.8) 43.901,30.878 44.228,30.878 R31.1@45.375,32.025
NetD6_2: D6.2 D8.1 | length 1.5
  Top Layer w0.3: D6.2@26.604,25.57 D8.1@28.133,25.57
NetD9_2: D9.2 R17.1 R36.2 | length 17.2
  Top Layer w0.2: v4(38.576,39.974) 38.662,40.059 38.662,41.364 R17.1@38.862,41.564
  Top Layer w0.4: D9.2@41.65,32.025 41.65,30.607 41.975,30.282 v2(41.975,30.225)
  Bottom Layer w0.2: v4(38.576,39.974) 38.576,36.155 37.536,35.114 37.536,34.442 38.18,33.798 40.752,33.798 41.15,33.4 R36.2@41.15,32.125
  Bottom Layer w0.4: R36.2@41.15,32.125 41.749,31.526 41.749,30.508 41.975,30.282 v2(41.975,30.225)
NetD10_1: D10.1 D16.2 | length 1.5
  Top Layer w0.3: D10.1@26.604,24.511 26.625,24.49 28.112,24.49 D16.2@28.133,24.468
NetQ1_1: Q1.1 R19.1 | length 1.4
  Top Layer w0.2: Q1.1@45.327,45.636 R19.1@45.327,47.053
NetR1_1: R1.1 R14.1 SW3.3 SW3.4 | length 12.2
  Top Layer w0.3: SW3.4@28.97,36.667 29.05,36.667 32.061,36.667 32.242,36.848 ; R14.1@31.066,39.8 R14.1@31.106,39.8 ; R1.1@31.256,41.309 31.256,39.95 R14.1@31.106,39.8 ; SW3.3@35.55,36.667 32.423,36.667 32.242,36.848 ; R14.1@31.106,39.8 31.895,39.8 32.242,39.452 32.242,36.848
NetR3_1: R3.1 R24.2 | length 5.6
  Bottom Layer w1: R3.1@33.75,13.725 37.99,13.725 38.743,14.478 R24.2@39,14.478
NetR5_1: R5.1 SW1.3 SW1.4 | length 14.6
  Top Layer w0.2: R5.1@62.267,37.938 63.427,37.938 64.281,37.084 67.524,37.084 SW1.4@69.25,38.81 SW1.3@69.25,32.31
NetR7_2: R7.2 R21.2 | length 2
  Top Layer w0.6: R7.2@40.005,20.612 41.557,20.612 41.707,20.762 R21.2@41.707,20.955
NetR9_1: R9.1 SW2.3 SW2.4 | length 32.7
  Top Layer w0.2: R9.1@18.26,32.42 18.26,32.32 18.85,31.73 18.85,31.589 19.238,31.201 v2(19.238,31.122)
  Bottom Layer w0.2: SW2.4@16.175,1.825 SW2.3@16.175,8.325 16.175,13.325 19.125,16.275 19.725,16.875 19.725,30.612 19.238,31.099 v2(19.238,31.122)
NetR10_1: R10.1 R12.2 SW1.1 SW1.2 | length 11.9
  Top Layer w0.2: SW1.2@64.75,38.81 65.007,38.81 65.638,39.442 67.066,39.442 67.183,39.559 R10.1@67.183,40.575
  Top Layer w0.6: R10.1@67.183,40.575 R10.1@67.183,40.675 R12.2@68.674,40.675
  Bottom Layer w0.2: SW1.1@64.75,32.31 SW1.2@64.75,38.81
NetR11_1: R11.1 R13.2 SW2.1 SW2.2 | length 35.4
  Top Layer w0.2: v1(25.89,32.436) 25.89,33.417 R13.2@26.001,33.528 27.397,33.528 R11.1@27.432,33.563
  Bottom Layer w0.2: SW2.2@20.675,1.825 SW2.1@20.675,8.325 21.35,9 21.35,27.896 v1(25.89,32.436)
NetR21_1: R21.1 R22.2 | length 3.1
  Top Layer w0.6: R21.1@44.78,20.828 44.78,20.587 44.93,20.437 46.369,20.437 46.874,20.942 47.36,20.942 R22.2@47.363,20.939
NetR22_1: R22.1 R23.1 | length 2.5
  Top Layer w0.6: R23.1@46.836,24.55 46.846,24.561 47.766,24.561 48.616,23.711 R22.1@48.963,23.711
NetR23_2: R23.2 R28.2 | length 2.6
  Top Layer w0.8: R28.2@41.55,25.925 43.839,25.925 R23.2@44.064,26.15
NetR28_1: R28.1 R29.2 | length 2
  Top Layer w0.8: R29.2@36.15,25.875 R28.1@38.121,25.875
